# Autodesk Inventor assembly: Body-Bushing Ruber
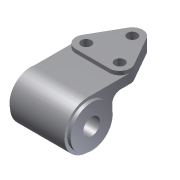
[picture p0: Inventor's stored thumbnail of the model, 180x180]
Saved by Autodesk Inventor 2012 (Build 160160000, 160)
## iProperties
Created: 2011-07
Part Number: Body-Bushing Ruber
Document SubType Name: Assembly
Designer: CadCim
Author: CadCim
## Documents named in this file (3)
- C:\Users\CadCim\Documents\SAILESH\inventor-2011-fact-prt\c09_inv_2011-prt\c09_inv_2012_prt\Tutorials\c09_tut03_inv\Anti Vibration Mount\Body-Bushing Ruber.iam
- C:\Users\CadCim\Documents\SAILESH\inventor-2011-fact-prt\c09_inv_2011-prt\c09_inv_2012_prt\Tutorials\c09_tut03_inv\Anti Vibration Mount\Body.ipt
- C:\Users\CadCim\Documents\SAILESH\inventor-2011-fact-prt\c09_inv_2011-prt\c09_inv_2012_prt\Tutorials\c09_tut03_inv\Anti Vibration Mount\Bushing Rubber.ipt
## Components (3 placed, 2 different names)
1. Body:1 — Insert:1, Insert:2
2. Bushing Rubber:1 — Insert:1
3. Bushing Rubber:2 — Insert:2
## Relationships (2: Insert 2)
- Insert:1: Body:1 ↔ Bushing Rubber:1
- Insert:2: Body:1 ↔ Bushing Rubber:2
